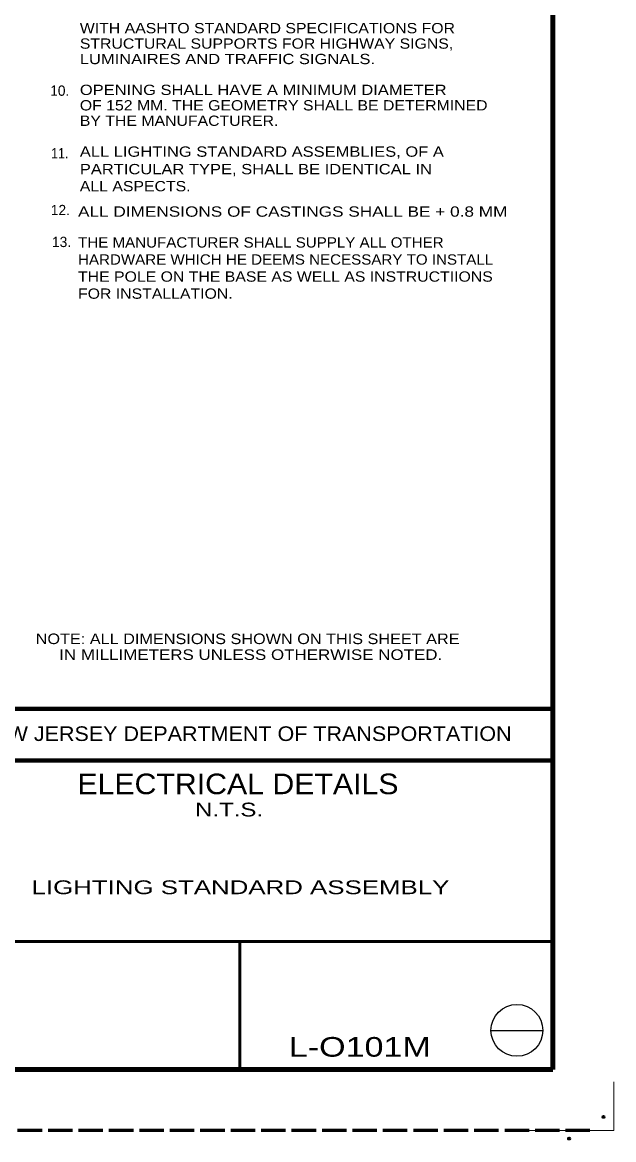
# Model space of a CAD drawing. Extents: x 312583 to 312854, y 144418 to 144597.
# Drawn here: x 312809.8 to 312853.5, y 144417.9 to 144500.4 of the extents above; entities that cross this region are included whole.
import ezdxf
from ezdxf.enums import TextEntityAlignment as Align

# ---------------------------------------------------------------- set-up
doc = ezdxf.new("R2010")
doc.units = 0
doc.header["$LTSCALE"] = 0.3
doc.header["$PDMODE"] = 32
doc.header["$PDSIZE"] = 0.15
doc.linetypes.add('LONG_DASHED', pattern=[7.5, 6, -1.5])
doc.layers.add('1', color=7, linetype='Continuous', lineweight=35)
doc.layers.add('2', color=7, linetype='Continuous')
doc.layers.add('5', color=7, linetype='Continuous')

msp = doc.modelspace()

# ---------------------------------------------------------------- linework, layer by layer
at = {"layer": '1', "lineweight": 80}
for p, q in [((312803.31, 144449.7246), (312849, 144449.7246)), ((312803.31, 144445.9146), (312849, 144445.9146))]:
    msp.add_line(p, q, dxfattribs=at)
at = {"layer": '1', "lineweight": 53}
for p, q in [((312849, 144432.5546), (312803.2881, 144432.5546)), ((312825.881, 144432.5546), (312825.881, 144423.0843))]:
    msp.add_line(p, q, dxfattribs=at)
at = {"layer": '1', "lineweight": 25}
msp.add_line((312844.4384, 144425.966), (312848.2794, 144425.966), dxfattribs=at)
at = {"layer": '1', "lineweight": 158}
msp.add_line((312616.5, 144423.0846), (312849, 144423.0846), dxfattribs=at)
at = {"layer": '1', "lineweight": 13}
for p in [(312853.5, 144422.1846), (312846.6, 144418.5846)]:
    msp.add_line(p, (312853.5, 144418.5846), dxfattribs=at)
at = {"layer": '1', "linetype": 'LONG_DASHED', "lineweight": 60}
msp.add_line((312851.75, 144418.5846), (312583.526, 144418.5846), dxfattribs=at)
at = {"layer": '1', "lineweight": 158}
msp.add_lwpolyline([(312849, 144423.0846), (312849, 144585.0846), (312616.5, 144585.0846), (312616.5, 144423.0846)], close=True, dxfattribs=at)
msp.add_lwpolyline([(312616.5, 144585.0846), (312616.5, 144423.0846), (312849, 144423.0846)], dxfattribs=at)
at = {"layer": '1', "lineweight": 25}
msp.add_circle((312846.3494, 144425.9805), 1.9159, dxfattribs=at)
at = {"layer": '1'}
for p in [(312852.75, 144419.5846), (312850.2, 144417.9846)]:
    msp.add_point(p, dxfattribs=at)

# ---------------------------------------------------------------- texts
for s, width, p in [('NOTE: ALL DIMENSIONS SHOWN ON THIS SHEET ARE', 1.15, (312810.7839, 144454.5093)), ('     IN MILLIMETERS UNLESS OTHERWISE NOTED.', 1.2, (312810.7838, 144453.3393))]:
    msp.add_text(s, height=0.78, dxfattribs=dict(at, width=width)).set_placement(p)
at = {"layer": '1', "width": 1.1}
for s, height, p in [('NEW JERSEY DEPARTMENT OF TRANSPORTATION', 1.08, (312826.2285, 144447.3546)), ('ELECTRICAL DETAILS', 1.52, (312825.7303, 144443.4248))]:
    msp.add_text(s, height=height, dxfattribs=at).set_placement(p, align=Align.CENTER)
at = {"layer": '2'}
for s, width, p in [('WITH AASHTO STANDARD SPECIFICATIONS FOR  ', 1.15, (312814.0451, 144499.6231)), ('STRUCTURAL SUPPORTS FOR HIGHWAY SIGNS,  ', 1.15, (312814.0451, 144498.4831)), ('LUMINAIRES AND TRAFFIC SIGNALS.   ', 1.2, (312814.0451, 144497.3431)), ('OPENING SHALL HAVE A MINIMUM DIAMETER   ', 1.2, (312814.0451, 144495.0631)), ('OF 152 MM. THE GEOMETRY SHALL BE DETERMINED ', 1.15, (312814.0451, 144493.9231)), ('BY THE MANUFACTURER.   ', 1.15, (312814.0451, 144492.7831)), ('ALL LIGHTING STANDARD ASSEMBLIES, OF A  ', 1.2, (312814.0451, 144490.5031)), ('PARTICULAR TYPE, SHALL BE IDENTICAL IN', 1.2, (312814.0451, 144489.2106)), ('ALL ASPECTS.', 1.15, (312814.0451, 144487.9506)), ('ALL DIMENSIONS OF CASTINGS SHALL BE + 0.8 MM  ', 1.25, (312813.9121, 144486.0748)), ('THE MANUFACTURER SHALL SUPPLY ALL OTHER', 1.1, (312813.9121, 144483.7948)), ('HARDWARE WHICH HE DEEMS NECESSARY TO INSTALL', 1.1, (312813.9121, 144482.5348)), ('THE POLE ON THE BASE AS WELL AS INSTRUCTIIONS', 1.15, (312813.9121, 144481.2748)), ('FOR INSTALLATION.', 1.15, (312813.9121, 144480.0148))]:
    msp.add_text(s, height=0.76, dxfattribs=dict(at, width=width)).set_placement(p)
for s, p in [('10.', (312812.5604, 144495.0062)), ('12.', (312812.6065, 144486.189)), ('13.', (312812.6951, 144483.8328))]:
    msp.add_text(s, height=0.76, dxfattribs=at).set_placement(p, align=Align.CENTER)
for s, height, width, p in [('11.', 0.76, 0.9, (312812.56, 144490.3829)), ('    N.T.S.  ', 1.02, 1.3, (312824.582, 144441.778)), ('          LIGHTING STANDARD ASSEMBLY          ', 1.02, 1.4, (312825.918, 144436.0399))]:
    msp.add_text(s, height=height, dxfattribs=dict(at, width=width)).set_placement(p, align=Align.CENTER)
at = {"layer": '5', "width": 1.3}
msp.add_text('L-O101M   ', height=1.449, dxfattribs=at).set_placement((312835.7876, 144424.0383), align=Align.CENTER)

doc.saveas('drawing.dxf')
